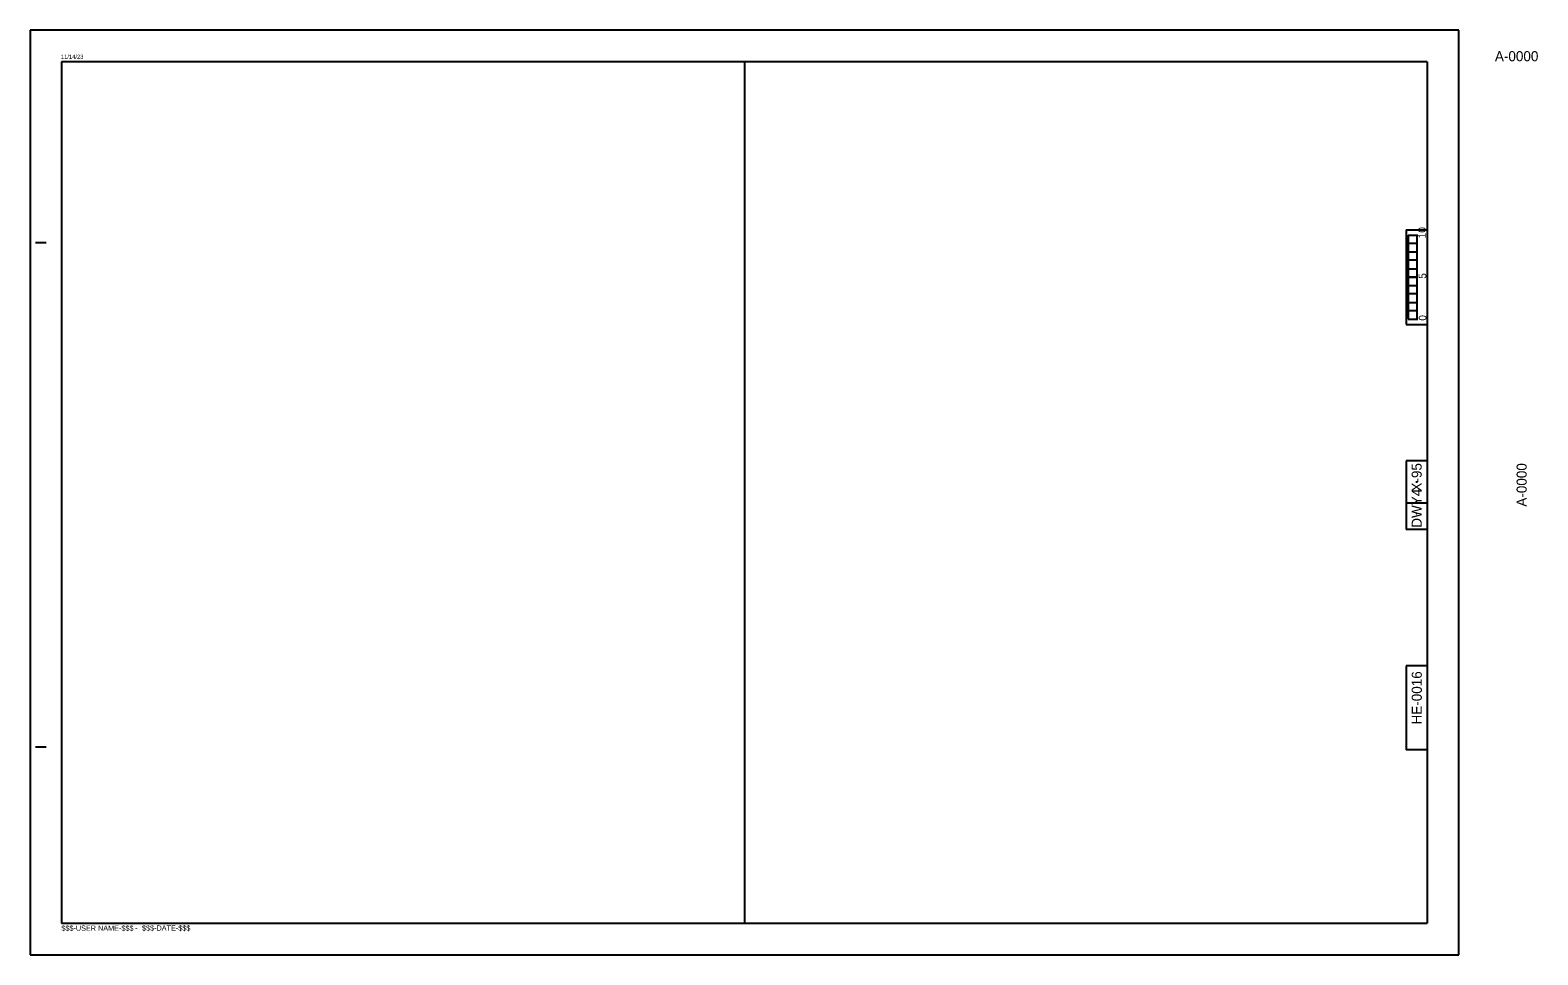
# Model space of a CAD drawing. Extents: x -2.69 to 2.99, y 0 to 1.83.
# Drawn here: x 0 to 2.99, y 0 to 1.833 of the extents above; entities that cross this region are included whole.
import ezdxf

# ---------------------------------------------------------------- set-up
doc = ezdxf.new("R2010")
doc.units = 0
for name, color, linetype in [('P_NCDOT_XS_Sheet_Alignment_Station_Label', 7, 'Continuous'), ('P_NCDOT_XS_Sheet_Annotation_Label', 7, 'Continuous'), ('Sheet_Grid_Major', 7, 'Continuous'), ('Sheet_Grid_Middle', 7, 'Continuous'), ('Sheet_Grid_Minor', 7, 'Continuous')]:
    doc.layers.add(name, color=color, linetype=linetype)

msp = doc.modelspace()

# ---------------------------------------------------------------- linework, layer by layer
at = {"layer": 'P_NCDOT_XS_Sheet_Alignment_Station_Label'}
for p, q in [((2.7333, 1.4271), (2.7522, 1.4271)), ((2.7333, 1.4271), (2.7333, 1.2604)), ((2.7417, 1.4271), (2.7504, 1.4271)), ((2.75, 1.4271), (2.75, 1.2604)), ((2.7333, 1.3437), (2.7522, 1.3437)), ((2.7333, 1.2604), (2.7522, 1.2604)), ((2.7417, 1.2604), (2.7504, 1.2604))]:
    msp.add_line(p, q, dxfattribs=at)
for points in [[(2.7333, 1.4271), (2.75, 1.4271), (2.75, 1.4104), (2.7333, 1.4104)], [(2.7333, 1.3937), (2.75, 1.3937), (2.75, 1.3771), (2.7333, 1.3771)], [(2.7333, 1.3604), (2.75, 1.3604), (2.75, 1.3437), (2.7333, 1.3437)], [(2.7333, 1.3271), (2.75, 1.3271), (2.75, 1.3104), (2.7333, 1.3104)], [(2.7333, 1.2937), (2.75, 1.2937), (2.75, 1.2771), (2.7333, 1.2771)]]:
    msp.add_lwpolyline(points, close=True, dxfattribs=at)
at = {"layer": 'P_NCDOT_XS_Sheet_Annotation_Label'}
for p, q in [((2.8333, 1.8333), (0, 1.8333)), ((0, 1.8333), (0, 0)), ((2.8333, 0), (2.8333, 1.8333)), ((1.4167, 1.7708), (1.4166, 0.0625)), ((0, 0), (2.8333, 0))]:
    msp.add_line(p, q, dxfattribs=at)
for centre in [(2.7499, 1.3437), (2.7499, 0.9375), (2.7499, 0.875), (2.75, 0.4897)]:
    msp.add_circle(centre, 0.0001, dxfattribs=at)
at = {"layer": 'Sheet_Grid_Minor'}
for p, q in [((0.0625, 1.7708), (0.0625, 0.0625)), ((2.7708, 1.7708), (0.0625, 1.7708)), ((0.1027, 1.7844), (0.1027, 1.7844)), ((2.7708, 1.7708), (2.7708, 0.0625)), ((2.7292, 1.4375), (2.7292, 1.25)), ((2.7292, 1.4375), (2.7708, 1.4375)), ((0.0108, 1.4125), (0.0317, 1.4126)), ((2.7292, 1.25), (2.7708, 1.25)), ((2.7292, 0.9792), (2.7292, 0.8435)), ((2.7708, 0.9792), (2.7292, 0.9792)), ((2.7708, 0.8958), (2.7292, 0.8958)), ((2.7708, 0.8435), (2.7292, 0.8435)), ((2.7292, 0.5729), (2.7292, 0.4062)), ((2.7708, 0.5729), (2.7292, 0.5729)), ((0.0109, 0.4125), (0.0317, 0.4125)), ((2.7708, 0.4062), (2.7292, 0.4062)), ((0.0625, 0.0625), (2.7708, 0.0625))]:
    msp.add_line(p, q, dxfattribs=at)

# ---------------------------------------------------------------- texts
at = {"layer": 'P_NCDOT_XS_Sheet_Alignment_Station_Label'}
for s, p in [('10', (2.7679, 1.4206)), ('5', (2.7689, 1.3404)), ('0', (2.7691, 1.2573))]:
    msp.add_text(s, height=0.015, rotation=90, dxfattribs=at).set_placement(p)
at = {"layer": 'Sheet_Grid_Major'}
msp.add_text('A-0000', height=0.02, dxfattribs=at).set_placement((2.9051, 1.7717))
msp.add_text('A-0000', height=0.02, rotation=90, dxfattribs=at).set_placement((2.9681, 0.8886))
at = {"layer": 'Sheet_Grid_Middle'}
for s, p in [('X-95', (2.7599, 0.9185)), ('DWY4', (2.76, 0.8468)), ('HE-0016', (2.7601, 0.4567))]:
    msp.add_text(s, height=0.02, rotation=90, dxfattribs=at).set_placement(p)
at = {"layer": 'Sheet_Grid_Minor'}
msp.add_text('11/14/23', height=0.00833, rotation=0, dxfattribs=at).set_placement((0.0609, 1.7764))
for s, height, p in [('$$$-USER NAME-$$$', 0.010417, (0.0619, 0.0477)), ('-', 0.0104, (0.2081, 0.0487)), ('$$$-DATE-$$$', 0.010417, (0.2218, 0.0479))]:
    msp.add_text(s, height=height, dxfattribs=at).set_placement(p)

doc.saveas('drawing.dxf')
